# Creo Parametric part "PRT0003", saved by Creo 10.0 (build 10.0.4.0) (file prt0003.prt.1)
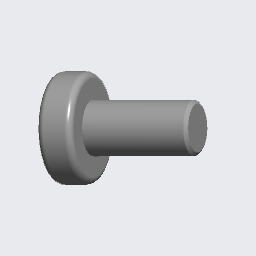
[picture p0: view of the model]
Units: millimeter Kilogram Sec (mmKs); MM, KILOGRAM, SECS

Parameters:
  MERGE_BASE_PART = "M3_SCREW"

Other named items: RIGHT, TOP, FRONT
